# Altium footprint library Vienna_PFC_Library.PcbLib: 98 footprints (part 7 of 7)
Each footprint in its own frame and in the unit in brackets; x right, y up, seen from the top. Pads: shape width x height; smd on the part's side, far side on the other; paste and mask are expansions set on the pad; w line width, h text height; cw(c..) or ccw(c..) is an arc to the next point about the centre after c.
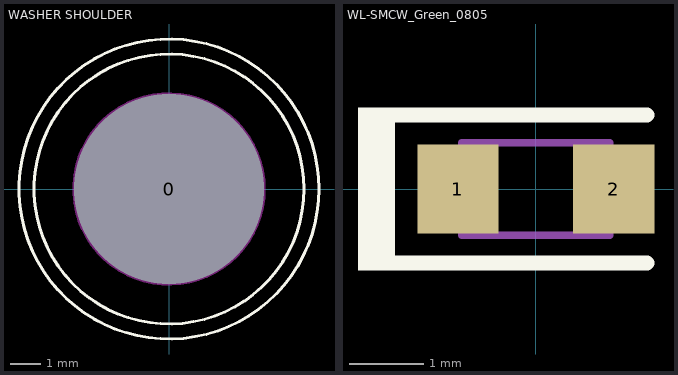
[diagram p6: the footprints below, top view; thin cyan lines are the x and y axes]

## WASHER SHOULDER [mm] "WASHER SHOULDER"
height 1
pads (1):
  round 4.35 hole 6.35: 0(0,0)
Top Overlay:
  circle w0.1: c0,0 r4.5
  circle w0.1: c0,0 r5
Keep-Out Layer:
  circle w0.1: c0,0 r3.175
3D body "M4_Screws.STEP": height 3.58, standoff -14.92, extent -4.504,-4.504 4.496,4.496

## WL-SMCW_Green_0805 [mm] "SMD, 2-Leads, Body 2x1.25mm"
height 0.8
pads (2):
  rect 1.1x1.2 smd: 1(-1.05,0) 2(1.05,0)
Top Overlay:
  rectangle: -2.4,-1.1 -2,1.1
  lines w0.2: 1.5,-1 -2,-1 -2,1 1.5,1
Mechanical 5:
  lines w0.1: -1,-0.625 -1,-0.425 -1,-0.35 -1,-0.2 ccw(c-1,0) -1,0.2 -1,0.35 -1,0.425 -1,0.625 1,0.625 1,0.2 ccw(c1,0) 1,-0.2 1,-0.625 -1,-0.625
3D body "WL-SMCW_0805.stp": height 0.7, standoff 0, extent -1,-0.625 1,0.625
